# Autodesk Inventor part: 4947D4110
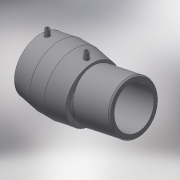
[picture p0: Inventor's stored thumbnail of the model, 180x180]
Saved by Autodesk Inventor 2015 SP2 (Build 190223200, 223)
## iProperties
Created: 2017-06
Part Number: 4947D4110
Material: Generic
Description: PLASSON ADJUSTABLE ELBOW (ONE SIDE) 110
Document SubType Name: Modeling
Designer: KIM
Mass: 55.0731 g
Surface Area: 148.067 cm^2
Volume: 55.0731 cm^3
Density: 1 g/cm^3
Appearance: Default
Author: KIM
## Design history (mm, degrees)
derived "4947D4.ipt"
feature "Solid1::4947D4.ipt"
tag "TaggingFeature1"
body "Solid1"
other parameters: "d0" = 144.9, "d3" = 85, "d4" = 42.5, "d5" = 126, "d8" = 168 deg, "d10" = 34, "d11" = 11.33333, "d29" = 83, "d30" = 15, "d31" = 55.2, "d34" = 5 deg, "d41" = 4, "d42" = 14, "d43" = 0, "d48" = 99, "d55" = 35.94, "d57" = 168 deg, "d62" = 3, "d63" = 0, "d65" = 276, "d67" = 99, "d68" = 135 deg, "d69" = 85, "d70" = 51.8, "d71" = 2.8, "L_" = 276, "L_1" = 85, "A_" = 83, "d_2" = 12, "L_0" = 148, "L_2" = 85, "d54" = 59.9, "d59" = 167.78449
